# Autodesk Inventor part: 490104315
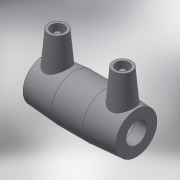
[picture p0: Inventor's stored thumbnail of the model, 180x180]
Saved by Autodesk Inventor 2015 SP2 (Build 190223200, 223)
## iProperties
Created: 2017-06
Part Number: 490104315
Material: Generic
Description: PLASSON COUPLER 315-315
Document SubType Name: Modeling
Designer: KIM
Mass: 55.0731 g
Surface Area: 148.067 cm^2
Volume: 55.0731 cm^3
Density: 1 g/cm^3
Appearance: Default
Author: KIM
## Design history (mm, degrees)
derived "490104.ipt"
feature "Solid1::490104.ipt"
tag "TaggingFeature1"
body "Solid1"
other parameters: "d0" = 282, "d1" = 315, "d2" = 387, "d3" = 139, "d4" = 94, "d5" = 348.3, "d6" = 299.25, "d7" = 315, "d8" = 168 deg, "d10" = 55.6, "d11" = 18.53333, "d13" = 282, "d14" = 17.6296, "d15" = 139, "d16" = 139, "d17" = 299.25, "d18" = 315, "d19" = 3.52592, "d20" = 168 deg, "d22" = 363.78, "d23" = 387, "d24" = 352.8666, "d25" = 135 deg, "d26" = 155.1, "d27" = 135 deg, "d29" = 184, "d30" = 14, "d31" = 98.7, "d34" = 5 deg, "d35" = 15, "d39" = 5 deg, "d41" = 4, "d42" = 14, "d43" = 0, "d45" = 4, "d46" = 14, "d47" = 0, "d48" = 3, "d49" = 0, "d50" = 3, "d51" = 0, "d52" = 40.31, "d53" = 10.0775, "d_" = 315, "L_" = 282, "L_1" = 139, "D_" = 387, "A_" = 184, "d_2" = 12
